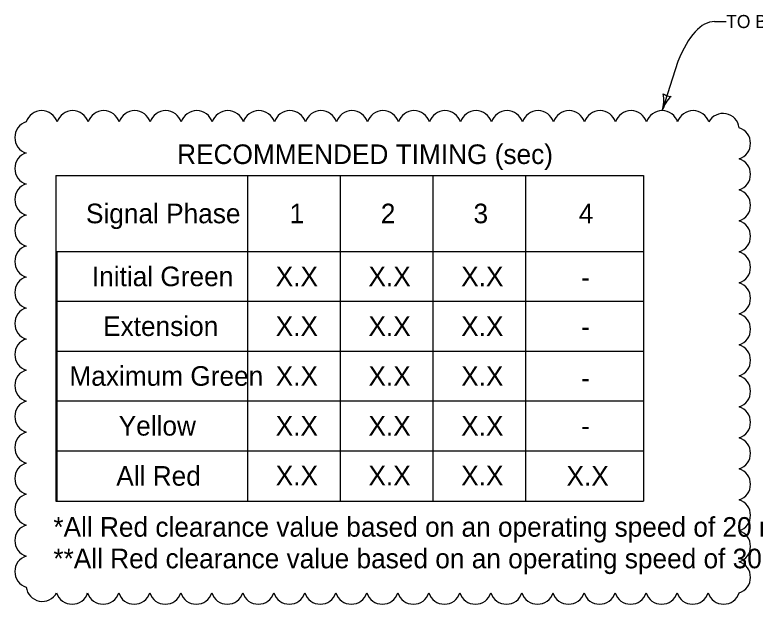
# Model space of a CAD drawing. Extents: x -2134934 to -2122394, y -2140205 to -2137036.
# Drawn here: x -2129568 to -2128661, y -2140205 to -2139483 of the extents above; entities that cross this region are included whole.
import ezdxf

# ---------------------------------------------------------------- set-up
doc = ezdxf.new("R2010")
doc.units = 0
doc.layers.add('BridgeSuperStructureExisting', color=7, linetype='Continuous')
doc.layers.add('dsnStdLabel', color=7, linetype='Continuous')

msp = doc.modelspace()

# ---------------------------------------------------------------- linework, layer by layer
at = {"layer": 'BridgeSuperStructureExisting'}
for p, q in [((-2128711.09, -2139491.35), (-2128696.87, -2139491.35)), ((-2128755.82, -2139540.49), (-2128775.22, -2139600.49)), ((-2129517.18, -2139679.89), (-2129517.18, -2140078.71)), ((-2129517.18, -2139679.89), (-2128798.05, -2139679.89)), ((-2129282.86, -2139679.89), (-2129282.86, -2140078.71)), ((-2129169.36, -2139679.89), (-2129169.36, -2140078.71)), ((-2129055.86, -2139679.89), (-2129055.86, -2140078.71)), ((-2128942.36, -2139679.89), (-2128942.36, -2140078.71)), ((-2128798.05, -2139679.89), (-2128798.05, -2140078.71)), ((-2129515.94, -2139772.98), (-2128798.05, -2139772.98)), ((-2129515.94, -2139772.98), (-2129515.94, -2139833.98)), ((-2129515.94, -2139833.98), (-2129515.94, -2139894.98)), ((-2129515.94, -2139833.98), (-2128798.05, -2139833.98)), ((-2129515.94, -2139894.98), (-2129515.94, -2139955.98)), ((-2129515.94, -2139894.98), (-2128798.05, -2139894.98)), ((-2129515.94, -2139955.98), (-2129515.94, -2140016.98)), ((-2129515.94, -2139955.98), (-2128798.05, -2139955.98)), ((-2129515.94, -2140016.98), (-2129515.94, -2140077.98)), ((-2129515.94, -2140016.98), (-2128798.05, -2140016.98)), ((-2129517.18, -2140078.71), (-2128798.05, -2140078.71))]:
    msp.add_line(p, q, dxfattribs=at)
for centre, radius, start, end in [((-2128815.66, -2139587.41), 42.5, 342.08492, 10.15741), ((-2128734.78, -2139613.56), 42.5, 134.01243, 162.08492), ((-2128764.25, -2139566.58), 16.42, 234.35157, 269.81827), ((-2129534.62, -2139620.39), 19.91, 17.5, 162.5), ((-2129496.65, -2139620.39), 19.91, 17.5, 162.5), ((-2129458.68, -2139620.39), 19.91, 17.5, 162.5), ((-2129420.71, -2139620.39), 19.91, 17.5, 162.5), ((-2129382.74, -2139620.39), 19.91, 17.5, 162.5), ((-2129344.77, -2139620.39), 19.91, 17.5, 162.5), ((-2129306.8, -2139620.39), 19.91, 17.5, 162.5), ((-2129268.83, -2139620.39), 19.91, 17.5, 162.5), ((-2129230.86, -2139620.39), 19.91, 17.5, 162.5), ((-2129192.89, -2139620.39), 19.91, 17.5, 162.5), ((-2129154.92, -2139620.39), 19.91, 17.5, 162.5), ((-2129116.95, -2139620.39), 19.91, 17.5, 162.5), ((-2129078.98, -2139620.39), 19.91, 17.5, 162.5), ((-2129041.01, -2139620.39), 19.91, 17.5, 162.5), ((-2129003.04, -2139620.39), 19.91, 17.5, 162.5), ((-2128965.07, -2139620.39), 19.91, 17.5, 162.5), ((-2128927.1, -2139620.39), 19.91, 17.5, 162.5), ((-2128889.13, -2139620.39), 19.91, 17.5, 162.5), ((-2128851.16, -2139620.39), 19.91, 17.5, 162.5), ((-2128813.19, -2139620.39), 19.91, 17.5, 162.5), ((-2128775.22, -2139620.39), 19.91, 17.5, 162.5), ((-2128737.25, -2139620.39), 19.91, 17.5, 162.5), ((-2128700.74, -2139623.84), 19.9, 6.71063, 151.71063), ((-2129547.62, -2139633.39), 19.91, 107.5, 252.5), ((-2128686.97, -2139640.5), 19.91, 287.5, 72.5), ((-2129547.62, -2139671.36), 19.91, 107.5, 252.5), ((-2128686.97, -2139678.47), 19.91, 287.5, 72.5), ((-2129547.62, -2139709.33), 19.91, 107.5, 252.5), ((-2128686.97, -2139716.44), 19.91, 287.5, 72.5), ((-2129547.62, -2139747.3), 19.91, 107.5, 252.5), ((-2128686.97, -2139754.41), 19.91, 287.5, 72.5), ((-2129547.62, -2139785.27), 19.91, 107.5, 252.5), ((-2128686.97, -2139792.38), 19.91, 287.5, 72.5), ((-2129547.62, -2139823.24), 19.91, 107.5, 252.5), ((-2128686.97, -2139830.35), 19.91, 287.5, 72.5), ((-2129547.62, -2139861.21), 19.91, 107.5, 252.5), ((-2128686.97, -2139868.32), 19.91, 287.5, 72.5), ((-2129547.62, -2139899.18), 19.91, 107.5, 252.5), ((-2128686.97, -2139906.29), 19.91, 287.5, 72.5), ((-2129547.62, -2139937.15), 19.91, 107.5, 252.5), ((-2128686.97, -2139944.26), 19.91, 287.5, 72.5), ((-2129547.62, -2139975.12), 19.91, 107.5, 252.5), ((-2128686.97, -2139982.23), 19.91, 287.5, 72.5), ((-2129547.62, -2140013.09), 19.91, 107.5, 252.5), ((-2128686.97, -2140020.2), 19.91, 287.5, 72.5), ((-2129547.62, -2140051.06), 19.91, 107.5, 252.5), ((-2128686.97, -2140058.17), 19.91, 287.5, 72.5), ((-2129547.62, -2140089.03), 19.91, 107.5, 252.5), ((-2128686.97, -2140096.14), 19.91, 287.5, 72.5), ((-2129547.62, -2140127), 19.91, 107.5, 252.5), ((-2128686.97, -2140134.11), 19.91, 287.5, 72.5), ((-2129547.62, -2140164.97), 19.91, 107.5, 252.5), ((-2128686.97, -2140172.08), 19.91, 287.5, 72.5), ((-2129533.84, -2140181.63), 19.9, 186.71063, 331.71063), ((-2129497.34, -2140185.07), 19.91, 197.5, 342.5), ((-2129459.37, -2140185.07), 19.91, 197.5, 342.5), ((-2129421.4, -2140185.07), 19.91, 197.5, 342.5), ((-2129383.43, -2140185.07), 19.91, 197.5, 342.5), ((-2129345.46, -2140185.07), 19.91, 197.5, 342.5), ((-2129307.49, -2140185.07), 19.91, 197.5, 342.5), ((-2129269.52, -2140185.07), 19.91, 197.5, 342.5), ((-2129231.55, -2140185.07), 19.91, 197.5, 342.5), ((-2129193.58, -2140185.07), 19.91, 197.5, 342.5), ((-2129155.61, -2140185.07), 19.91, 197.5, 342.5), ((-2129117.64, -2140185.07), 19.91, 197.5, 342.5), ((-2129079.67, -2140185.07), 19.91, 197.5, 342.5), ((-2129041.7, -2140185.07), 19.91, 197.5, 342.5), ((-2129003.73, -2140185.07), 19.91, 197.5, 342.5), ((-2128965.76, -2140185.07), 19.91, 197.5, 342.5), ((-2128927.79, -2140185.07), 19.91, 197.5, 342.5), ((-2128889.82, -2140185.07), 19.91, 197.5, 342.5), ((-2128851.85, -2140185.07), 19.91, 197.5, 342.5), ((-2128813.87, -2140185.07), 19.91, 197.5, 342.5), ((-2128775.9, -2140185.07), 19.91, 197.5, 342.5), ((-2128737.93, -2140185.07), 19.91, 197.5, 342.5), ((-2128699.96, -2140185.07), 19.91, 197.5, 342.5)]:
    msp.add_arc(centre, radius, start, end, dxfattribs=at)
msp.add_ellipse((-2128711.09, -2139704.29), major_axis=(0, 212.93), ratio=0.328743, start_param=0, end_param=0.693162, dxfattribs=at)

# ---------------------------------------------------------------- texts
msp.add_text('TO BE UPDATED ONCE TIMING PROVIDED BY IOWA DOT', height=16, dxfattribs=at).set_placement((-2128696.87, -2139499.35))
at = {"layer": 'dsnStdLabel'}
for s, p in [('RECOMMENDED TIMING (sec)', (-2129368.81, -2139665.87)), ('Signal Phase', (-2129480.42, -2139738.43)), ('1', (-2129231.21, -2139738.43)), ('2', (-2129119.53, -2139738.43)), ('3', (-2129006.1, -2139738.43)), ('4', (-2128877.17, -2139738.43)), ('Initial Green', (-2129473.18, -2139815.48)), ('X.X', (-2129248.19, -2139815.48)), ('X.X', (-2129134.69, -2139815.48)), ('X.X', (-2129021.19, -2139815.48)), ('-', (-2128874.35, -2139816.51)), ('Extension', (-2129459.43, -2139876.48)), ('X.X', (-2129248.19, -2139876.48)), ('X.X', (-2129134.69, -2139876.48)), ('X.X', (-2129021.19, -2139876.48)), ('-', (-2128874.35, -2139876.86)), ('Maximum Green', (-2129500.66, -2139937.48)), ('X.X', (-2129248.19, -2139937.48)), ('X.X', (-2129134.69, -2139937.48)), ('X.X', (-2129021.19, -2139937.48)), ('-', (-2128874.35, -2139939.92)), ('Yellow', (-2129440.37, -2139998.48)), ('X.X', (-2129248.19, -2139998.48)), ('X.X', (-2129134.69, -2139998.48)), ('X.X', (-2129021.19, -2139998.48)), ('-', (-2128874.35, -2139998.48)), ('All Red', (-2129443.32, -2140059.84)), ('X.X', (-2129248.19, -2140059.48)), ('X.X', (-2129134.69, -2140059.48)), ('X.X', (-2129021.19, -2140059.48)), ('X.X', (-2128892.28, -2140059.84)), ('*All Red clearance value based on an operating speed of 20 mph.', (-2129520.31, -2140122.32)), ('**All Red clearance value based on an operating speed of 30 mph.', (-2129520.31, -2140161))]:
    msp.add_text(s, height=24, dxfattribs=at).set_placement(p)

doc.saveas('drawing.dxf')
